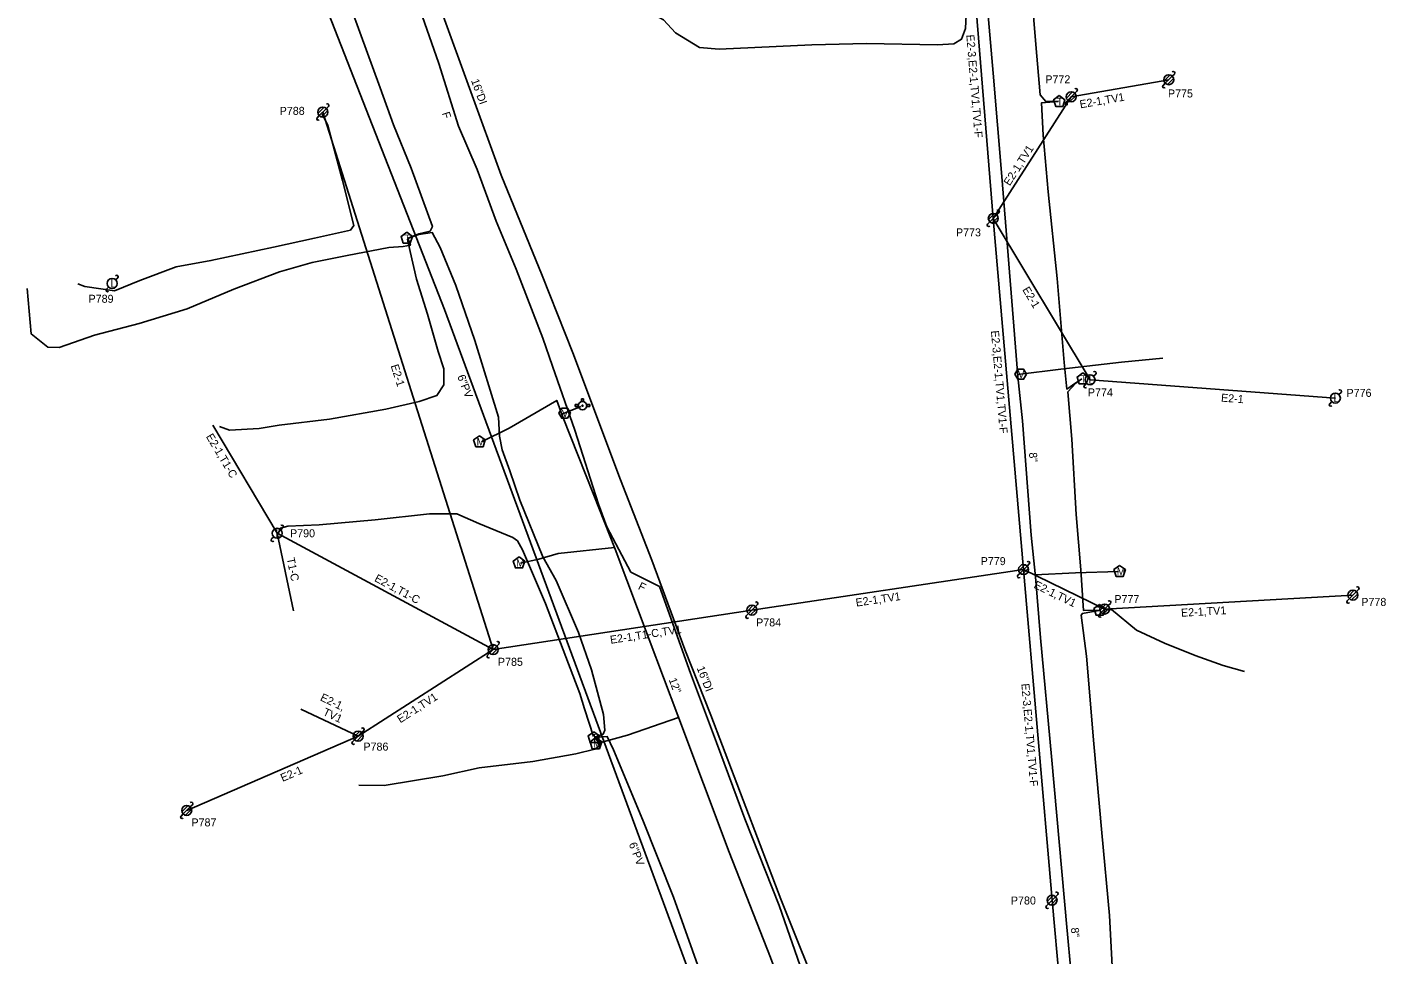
# Model space of a CAD drawing. Extents: x 1741604 to 1825760, y 1164229 to 1194908.
# Drawn here: x 1755844 to 1756523, y 1167516 to 1167980 of the extents above; entities that cross this region are included whole.
import ezdxf

# ---------------------------------------------------------------- set-up
doc = ezdxf.new("R2010")
doc.units = 0
for name, color, linetype in [('RD_EX_SU_Elec', 7, 'Continuous'), ('RD_EX_SU_H2O', 7, 'Continuous'), ('RD_EX_SU_Ovhd', 7, 'Continuous'), ('RD_EX_SU_Pole', 7, 'Continuous'), ('RD_EX_SU_Sewer', 7, 'Continuous'), ('RD_EX_SU_Telecom', 7, 'Continuous'), ('RD_EX_SU_TX_H2O', 7, 'Continuous'), ('RD_EX_SU_TX_Pole', 7, 'Continuous'), ('RD_EX_SU_TX_Sewer', 7, 'Continuous'), ('RD_EX_SU_TX_Telecom', 7, 'Continuous')]:
    doc.layers.add(name, color=color, linetype=linetype)

# ---------------------------------------------------------------- blocks, each defined once
blk = doc.blocks.new('SUE_TPP')
at = {"layer": 'RD_EX_SU_Telecom'}
blk.add_lwpolyline([(0, 3), (-2.85, 0.93), (-1.76, -2.43), (1.76, -2.43), (2.85, 0.93)], close=True, dxfattribs=at)
blk.add_text('T', height=3.75, dxfattribs=at).set_placement((-1.25, -1.88))
blk = doc.blocks.new('SUE_WV')
at = {"layer": 'RD_EX_SU_H2O'}
blk.add_lwpolyline([(2.89, 0), (1.44, 2.5), (-1.44, 2.5), (-2.89, 0), (-1.44, -2.5), (1.44, -2.5)], close=True, dxfattribs=at)
blk.add_text('V', height=3.75, dxfattribs=at).set_placement((-1.43, -1.88))
blk = doc.blocks.new('SUE_WM')
at = {"layer": 'RD_EX_SU_H2O'}
blk.add_lwpolyline([(0, 3.05), (-2.9, 0.94), (-1.79, -2.47), (1.79, -2.47), (2.9, 0.94)], close=True, dxfattribs=at)
blk.add_text('M', height=3.75, dxfattribs=at).set_placement((-1.43, -1.88))
blk = doc.blocks.new('SUE_PP')
at = {"layer": 'RD_EX_SU_Pole'}
for p, q in [((-2.41, -0.65), (0.65, 2.41)), ((-1.77, -1.77), (1.77, 1.77)), ((-0.65, -2.41), (2.41, 0.65)), ((1.77, 1.77), (2.83, 2.83)), ((-2.83, -2.83), (-1.77, -1.77))]:
    blk.add_line(p, q, dxfattribs=at)
blk.add_circle((0, 0), 2.5, dxfattribs=at)
for centre, start, end in [((2.3, 3.36), 315, 135), ((-2.3, -3.36), 135, 315)]:
    blk.add_arc(centre, 0.75, start, end, dxfattribs=at)
blk = doc.blocks.new('SUE_WFH')
at = {"layer": 'RD_EX_SU_H2O'}
for p, q in [((-2.01, 0.6), (-3.65, 0.6)), ((-3.65, 0.6), (-3.65, -0.45)), ((-0.48, 3.38), (-0.48, 2.04)), ((0.57, 3.38), (-0.48, 3.38)), ((0.57, 2.02), (0.57, 3.38)), ((3.7, 0.6), (2.01, 0.6)), ((3.7, -0.45), (3.7, 0.6)), ((-3.65, -0.45), (-2.05, -0.45)), ((2.05, -0.45), (3.7, -0.45))]:
    blk.add_line(p, q, dxfattribs=at)
for radius in [2.1, 0.263]:
    blk.add_circle((0, 0), radius, dxfattribs=at)
for start, end in [(163.3387, 192.31502), (74.24552, 103.21276), (347.68498, 16.6613)]:
    blk.add_arc((0, 0), 2.1, start, end, dxfattribs=at)

msp = doc.modelspace()

# ---------------------------------------------------------------- linework, layer by layer
at = {"layer": 'RD_EX_SU_Elec'}
msp.add_lwpolyline([(1755869.57, 1167851.16), (1755873.19, 1167849.88), (1755887.92, 1167847.77), (1755900.58, 1167852.96), (1755918.67, 1167859.68), (1755936.12, 1167862.87), (1755967.46, 1167869.61), (1755987.87, 1167873.98), (1756005.8, 1167878.1), (1756007.57, 1167880.39), (1756001.85, 1167902.91), (1755994.55, 1167930.43), (1755991.77, 1167936.28)], dxfattribs=at)
at = {"layer": 'RD_EX_SU_H2O'}
msp.add_line((1756111.54, 1167786.08), (1756120.89, 1167789.84), dxfattribs=at)
for points in [[(1756317.85, 1168067.08), (1756319.54, 1168050.19), (1756320.11, 1168042.67), (1756320.97, 1168030.07), (1756323.39, 1167998.84), (1756327.05, 1167956.56), (1756331.25, 1167904.83), (1756337.4, 1167830.13), (1756339.37, 1167804.89), (1756341.64, 1167782.73), (1756346.05, 1167725.54), (1756348.16, 1167704.76), (1756350.69, 1167674.25), (1756356.07, 1167614.92), (1756363.99, 1167527.76)], [(1756050.84, 1167988.86), (1756081.08, 1167905.61), (1756101.58, 1167855.44), (1756116.98, 1167816.66), (1756140.78, 1167753.22), (1756156.44, 1167713.09), (1756172.97, 1167668.41), (1756185.91, 1167635.6), (1756220.9, 1167543.58), (1756264.25, 1167435.38), (1756279.82, 1167397.12), (1756291.55, 1167363.49), (1756304.82, 1167319.34), (1756315.11, 1167296.28), (1756338.43, 1167239.43), (1756353.36, 1167188.5), (1756363.56, 1167189.08), (1756377.88, 1167188.77), (1756395.74, 1167189.62), (1756414.79, 1167190.46), (1756429.52, 1167190.99), (1756434.13, 1167122.57), (1756440.84, 1167042.69)], [(1756339.29, 1167805.94), (1756360.77, 1167808.6), (1756391.2, 1167811.99), (1756411.72, 1167814.03)], [(1756071.31, 1167772.16), (1756085.11, 1167779.07), (1756108.91, 1167792.94), (1756111.78, 1167785), (1756127.48, 1167745.51), (1756138.1, 1167718.5), (1756155.05, 1167673.34), (1756169.44, 1167635.39), (1756195.1, 1167567.1), (1756215.65, 1167514.35), (1756247.83, 1167428.43), (1756274.14, 1167357.35), (1756290.72, 1167313.58), (1756321.91, 1167230.75), (1756342.14, 1167174.56), (1756357.52, 1167133.56), (1756360.24, 1167126.4), (1756375.13, 1167136.28), (1756391.03, 1167147.63), (1756398.81, 1167147.78)], [(1756090.76, 1167711.58), (1756099.91, 1167713.6), (1756109.61, 1167716.33), (1756137.76, 1167719.35)], [(1756348.06, 1167705.73), (1756368.09, 1167706.65), (1756389.58, 1167707.36)], [(1756129.1, 1167621.41), (1756144.22, 1167625.61), (1756169.8, 1167634.44)], [(1756363.91, 1167527.82), (1756365.79, 1167507.89), (1756368.78, 1167467.42), (1756370.98, 1167441.15), (1756376.52, 1167385.51), (1756383.76, 1167307.51), (1756390.19, 1167237.32), (1756392.83, 1167205.42), (1756394.81, 1167177.82), (1756398.97, 1167146.58), (1756403.93, 1167098.11), (1756407.85, 1167047.93), (1756412.78, 1166988.79), (1756417.67, 1166944.94), (1756423.69, 1166896.82), (1756432.52, 1166846.14), (1756436.46, 1166827.08), (1756441.46, 1166798.75), (1756455, 1166743.89), (1756461.58, 1166718.69), (1756465.96, 1166702.52), (1756470.95, 1166683.5), (1756477.35, 1166658.41), (1756487.5, 1166618.6)]]:
    msp.add_lwpolyline(points, dxfattribs=at)
at = {"layer": 'RD_EX_SU_Ovhd'}
for p, q in [((1756317.86, 1167996.94), (1756327.05, 1167883.97)), ((1756366, 1167944.76), (1756414.72, 1167953.29)), ((1756327.05, 1167883.97), (1756366, 1167944.76)), ((1755992.03, 1167937.09), (1756077.13, 1167668.31)), ((1756327.05, 1167883.97), (1756342.18, 1167708.36)), ((1756327.05, 1167883.97), (1756375.39, 1167803.26)), ((1756375.39, 1167803.26), (1756497.97, 1167794.1)), ((1755937.06, 1167780.6), (1755969.27, 1167726.49)), ((1755969.27, 1167726.49), (1756077.13, 1167668.31)), ((1755969.27, 1167726.49), (1755977.32, 1167687.7)), ((1756206.43, 1167688.08), (1756342.18, 1167708.36)), ((1756342.18, 1167708.36), (1756356.4, 1167543.03)), ((1756342.18, 1167708.36), (1756382.71, 1167688.62)), ((1756382.71, 1167688.62), (1756506.75, 1167695.61)), ((1756077.13, 1167668.31), (1756206.43, 1167688.08)), ((1756009.64, 1167625.05), (1756077.13, 1167668.31)), ((1755981.08, 1167638.61), (1756009.64, 1167625.05)), ((1755924.02, 1167587.93), (1756009.64, 1167625.05)), ((1756356.4, 1167543.03), (1756373.78, 1167356.82))]:
    msp.add_line(p, q, dxfattribs=at)
at = {"layer": 'RD_EX_SU_Pole'}
for p, q in [((1756416.48, 1167955.06), (1756417.54, 1167956.12)), ((1756411.89, 1167950.46), (1756412.95, 1167951.52)), ((1756412.3, 1167952.64), (1756415.36, 1167955.71)), ((1756412.95, 1167951.52), (1756416.48, 1167955.06)), ((1756414.07, 1167950.88), (1756417.13, 1167953.94)), ((1756363.17, 1167941.93), (1756364.24, 1167942.99)), ((1756363.59, 1167944.11), (1756366.65, 1167947.17)), ((1756364.24, 1167942.99), (1756367.77, 1167946.52)), ((1756365.36, 1167942.34), (1756368.42, 1167945.4)), ((1756367.77, 1167946.52), (1756368.83, 1167947.59)), ((1755989.61, 1167936.44), (1755992.67, 1167939.51)), ((1755990.26, 1167935.32), (1755993.8, 1167938.86)), ((1755991.38, 1167934.68), (1755994.44, 1167937.74)), ((1755993.8, 1167938.86), (1755994.86, 1167939.92)), ((1755989.2, 1167934.26), (1755990.26, 1167935.32)), ((1756324.22, 1167881.14), (1756325.28, 1167882.2)), ((1756324.63, 1167883.32), (1756327.69, 1167886.38)), ((1756325.28, 1167882.2), (1756328.81, 1167885.74)), ((1756326.4, 1167881.56), (1756329.46, 1167884.62)), ((1756328.81, 1167885.74), (1756329.87, 1167886.8)), ((1755888.51, 1167853.18), (1755889.57, 1167854.24)), ((1755883.92, 1167848.58), (1755884.98, 1167849.64)), ((1756372.56, 1167800.43), (1756373.62, 1167801.5)), ((1756377.16, 1167805.03), (1756378.22, 1167806.09)), ((1756499.74, 1167795.87), (1756500.8, 1167796.93)), ((1756495.14, 1167791.27), (1756496.21, 1167792.33)), ((1755971.04, 1167728.26), (1755972.1, 1167729.32)), ((1755966.44, 1167723.67), (1755967.5, 1167724.73))]:
    msp.add_line(p, q, dxfattribs=at)
for centre in [(1756414.72, 1167953.29), (1756366, 1167944.76), (1755992.03, 1167937.09), (1756327.05, 1167883.97), (1755886.75, 1167851.41), (1756375.39, 1167803.26), (1756497.97, 1167794.1), (1755969.27, 1167726.49)]:
    msp.add_circle(centre, 2.5, dxfattribs=at)
for centre, start, end in [((1756417.01, 1167956.65), 315, 135), ((1756412.42, 1167949.93), 135, 315), ((1756368.3, 1167948.12), 315, 135), ((1755994.33, 1167940.45), 315, 135), ((1756363.71, 1167941.4), 135, 315), ((1755989.73, 1167933.73), 135, 315), ((1756329.34, 1167887.33), 315, 135), ((1756324.75, 1167880.61), 135, 315), ((1755889.04, 1167854.77), 315, 135), ((1755884.45, 1167848.05), 135, 315), ((1756377.69, 1167806.62), 315, 135), ((1756373.09, 1167799.9), 135, 315), ((1756500.27, 1167797.46), 315, 135), ((1756495.67, 1167790.74), 135, 315), ((1755971.57, 1167729.85), 315, 135), ((1755966.97, 1167723.14), 135, 315)]:
    msp.add_arc(centre, 0.75, start, end, dxfattribs=at)
at = {"layer": 'RD_EX_SU_Sewer'}
for points in [[(1755918.27, 1168182.4), (1756052.9, 1167838.38)], [(1756052.9, 1167838.38), (1756224.72, 1167372.47), (1756323.52, 1167096.55), (1756376.52, 1166947.01), (1756475.17, 1166587.83)]]:
    msp.add_lwpolyline(points, dxfattribs=at)
at = {"layer": 'RD_EX_SU_Telecom'}
for points in [[(1756338.16, 1168189.78), (1756333.21, 1168189.81), (1756330.86, 1168187.79), (1756330.68, 1168184.52), (1756333.54, 1168148.9), (1756336.25, 1168107.92), (1756338.14, 1168089.1), (1756341.61, 1168045.19), (1756342.02, 1168029.89), (1756344.16, 1168021.72), (1756348.34, 1167970.86), (1756350.41, 1167945.66), (1756353.23, 1167942.43), (1756359.64, 1167942.51)], [(1756034.61, 1167874.06), (1756040.08, 1167876.29), (1756045.63, 1167877.54), (1756046.82, 1167879.95), (1756036.25, 1167909.07), (1756027.29, 1167930.71), (1756020.62, 1167949.2), (1756010.49, 1167977), (1756001.55, 1168001.89), (1755990.3, 1168030.08), (1755982.09, 1168049.19), (1755980.19, 1168050.16), (1755973.48, 1168046.32)], [(1756158.59, 1167985.22), (1756162.2, 1167983.17), (1756168.33, 1167976.76), (1756180.21, 1167969.34), (1756190.12, 1167968.53), (1756236.31, 1167970.8), (1756263.75, 1167971.46), (1756299.2, 1167970.68), (1756307.27, 1167971.19), (1756311.09, 1167973.51), (1756313.18, 1167978.88), (1756313.61, 1167989.06), (1756314.16, 1167997.74), (1756316.41, 1167997.29)], [(1756039.32, 1167991.87), (1756050.05, 1167961.32), (1756059.83, 1167929.98), (1756069.2, 1167908.38), (1756078.7, 1167882.57), (1756088.71, 1167858.62), (1756102.02, 1167823.98), (1756106.74, 1167810.01), (1756117.97, 1167778.02), (1756129.82, 1167741.09), (1756134.01, 1167729.65), (1756145.95, 1167707.06), (1756160.25, 1167699.88), (1756175.68, 1167656.58), (1756188.68, 1167621.82), (1756202.92, 1167583.73), (1756219.98, 1167540.39), (1756233.26, 1167502.58)], [(1756359.48, 1167942.44), (1756351.11, 1167941.7), (1756351.95, 1167925.63), (1756354.4, 1167897.16), (1756358.92, 1167853.95), (1756362.5, 1167811.93), (1756363.77, 1167798.56), (1756368.25, 1167801.76), (1756371.25, 1167803.66)], [(1756034.53, 1167873.86), (1756040.08, 1167875.94), (1756046.7, 1167876.83), (1756050.72, 1167869.39), (1756058.52, 1167850.38), (1756068.07, 1167822.86), (1756079.87, 1167784.61), (1756080.23, 1167775.03), (1756081.57, 1167768.15), (1756085.55, 1167757.65), (1756090.48, 1167743.05), (1756101.96, 1167714.71), (1756108.69, 1167702.97), (1756119.73, 1167676.96), (1756126.29, 1167658.16), (1756132.36, 1167635.96), (1756132.95, 1167628.04), (1756132.08, 1167626), (1756127.76, 1167624.57)], [(1755844.3, 1167848.97), (1755846.32, 1167826.16), (1755854.61, 1167819.58), (1755860.32, 1167819.34), (1755877.92, 1167825.49), (1755900.21, 1167831.38), (1755924.21, 1167838.68), (1755947.5, 1167848.57), (1755970.39, 1167857.17), (1755986.75, 1167861.86), (1756004.23, 1167865.47), (1756024.94, 1167869.39), (1756032.13, 1167869.89), (1756035.8, 1167870.54), (1756034.7, 1167873.57)], [(1756034.35, 1167873.52), (1756035.66, 1167867.47), (1756038.81, 1167853.61), (1756044.27, 1167836.05), (1756049.68, 1167817.45), (1756052.45, 1167808.8), (1756052.53, 1167800.7), (1756049, 1167795.32), (1756040.22, 1167792.38), (1756023.57, 1167788.59), (1755995.41, 1167783.6), (1755970.21, 1167780.51), (1755960.21, 1167778.83), (1755945.42, 1167778.1), (1755940.33, 1167779.88)], [(1756371.22, 1167803.69), (1756368.25, 1167801.64), (1756364.32, 1167797.23), (1756366.22, 1167773.48), (1756368.54, 1167735.91), (1756370.77, 1167708.23), (1756372.16, 1167687.85), (1756379.89, 1167688.13)], [(1755969.89, 1167726.65), (1755970.91, 1167729.13), (1755974.51, 1167729.99), (1755990.23, 1167730.65), (1756018.14, 1167733.24), (1756045.36, 1167736.26), (1756058.92, 1167736.26), (1756070, 1167731.46), (1756087.05, 1167724.47), (1756089.36, 1167722.65), (1756091.74, 1167718.3), (1756103.28, 1167691.37), (1756113.45, 1167664.75), (1756120.39, 1167646.36), (1756122.75, 1167638.68), (1756127.3, 1167624.92)], [(1756379.84, 1167687.97), (1756371.61, 1167686.43), (1756371.04, 1167685.63), (1756373.7, 1167665.14), (1756377.25, 1167621.18), (1756381.27, 1167576.66), (1756385.09, 1167535.47), (1756386.8, 1167503.76), (1756389.57, 1167497.42), (1756391.33, 1167485.77), (1756391.87, 1167476.99), (1756394.9, 1167432.18), (1756398.78, 1167388.08), (1756403.08, 1167343.13), (1756406.4, 1167302.54), (1756409.67, 1167260.19), (1756412.65, 1167233.18), (1756415.46, 1167205.3), (1756418.94, 1167164.23), (1756422.06, 1167133.72), (1756424.59, 1167105.7), (1756427.38, 1167076.61), (1756430.2, 1167046.88)], [(1756383.1, 1167688.32), (1756386.12, 1167688.46), (1756398.58, 1167678.13), (1756412.62, 1167671.56), (1756428, 1167665.46), (1756441.94, 1167660.34), (1756452.56, 1167657.36)], [(1756010.05, 1167600.63), (1756022.7, 1167600.39), (1756052.08, 1167605.26), (1756070.07, 1167609.2), (1756096.95, 1167612.44), (1756118.49, 1167616.28), (1756127.92, 1167618.51), (1756130.07, 1167620.07), (1756130.01, 1167622.26), (1756127.75, 1167624.11)], [(1756127.86, 1167624.47), (1756134.12, 1167624.83), (1756137.29, 1167618.27), (1756151.91, 1167583.07), (1756167.31, 1167544.54), (1756181.93, 1167503.45), (1756190.52, 1167477.21), (1756195.07, 1167463.69), (1756198.66, 1167456.38), (1756204.33, 1167443.81), (1756202.19, 1167439.67), (1756198.01, 1167436.74)]]:
    msp.add_lwpolyline(points, dxfattribs=at)

# ---------------------------------------------------------------- block references
at = {"layer": 'RD_EX_SU_H2O'}
for name, p in [('SUE_WV', (1756340.74, 1167806.05)), ('SUE_WFH', (1756121.78, 1167790.32)), ('SUE_WV', (1756112.82, 1167786.49)), ('SUE_WM', (1756070.3, 1167772.21)), ('SUE_WM', (1756090.06, 1167711.63)), ('SUE_WM', (1756390.2, 1167707.41)), ('SUE_WM', (1756128.47, 1167621.27))]:
    msp.add_blockref(name, p, dxfattribs=at)
at = {"layer": 'RD_EX_SU_Pole'}
for p in [(1756342.18, 1167708.36), (1756506.75, 1167695.61), (1756206.43, 1167688.08), (1756382.71, 1167688.62), (1756077.13, 1167668.31), (1756009.64, 1167625.05), (1755924.02, 1167587.93), (1756356.4, 1167543.03)]:
    msp.add_blockref('SUE_PP', p, dxfattribs=at)
at = {"layer": 'RD_EX_SU_Telecom'}
for p in [(1756360.03, 1167942.36), (1756033.97, 1167874.01), (1756371.77, 1167803.65), (1756380.17, 1167687.93), (1756127.44, 1167624.3)]:
    msp.add_blockref('SUE_TPP', p, dxfattribs=at)

# ---------------------------------------------------------------- texts
at = {"layer": 'RD_EX_SU_Ovhd'}
for s, rotation, p in [('E2-3,E2-1,TV1,TV1-F', 274.64996, (1756313.57, 1167975.68)), ('E2-1,TV1', 9.9369, (1756370.58, 1167938.96)), ('E2-1,TV1', 57.34496, (1756335.26, 1167899.93)), ('E2-1', 300.92124, (1756341.41, 1167848.31)), ('E2-3,E2-1,TV1,TV1-F', 274.92539, (1756325.87, 1167827.73)), ('E2-1', 287.56914, (1756025.89, 1167810.27)), ('E2-1', 355.72628, (1756440.74, 1167792.36)), ('E2-1,T1-C', 300.76396, (1755933.49, 1167774.88)), ('T1-C', 281.71511, (1755973.92, 1167713.91)), ('E2-1,T1-C', 331.65738, (1756017.47, 1167702.77)), ('E2-1,TV1', 334.02741, (1756346.93, 1167699.37)), ('E2-1,TV1', 8.49892, (1756258.61, 1167689.81)), ('E2-1,TV1', 3.22525, (1756420.98, 1167684.76)), ('E2-1,T1-C,TV1', 8.68997, (1756135.88, 1167671.22)), ('E2-3,E2-1,TV1,TV1-F', 274.91654, (1756341.07, 1167651.24)), ('E2-1,', 334.60195, (1755990.37, 1167643.05)), ('E2-1,TV1', 32.66151, (1756030.74, 1167631.45)), ('TV1', 334.60195, (1755991.71, 1167635.78)), ('E2-1', 23.4387, (1755971.93, 1167602.16))]:
    msp.add_text(s, height=4, rotation=rotation, dxfattribs=at).set_placement(p)
at = {"layer": 'RD_EX_SU_Pole'}
for p in [(1755885.88, 1167849.41), (1756374.53, 1167801.26), (1756497.11, 1167792.1), (1755968.41, 1167724.49)]:
    msp.add_text('L', height=4, dxfattribs=at).set_placement(p)
at = {"layer": 'RD_EX_SU_TX_H2O'}
for s, rotation, p in [('16"DI', 289.9624, (1756066.03, 1167952.9)), ('8"', 274.41179, (1756344.87, 1167766.81)), ('16"DI', 291.54117, (1756178.76, 1167659.18)), ('12"', 290.77175, (1756164.77, 1167653.35)), ('8"', 275.38113, (1756365.79, 1167529.19))]:
    msp.add_text(s, height=4, rotation=rotation, dxfattribs=at).set_placement(p)
at = {"layer": 'RD_EX_SU_TX_Pole'}
for s, p in [('P772', (1756353.04, 1167951.48)), ('P775', (1756414.33, 1167944.42)), ('P788', (1755970.47, 1167935.72)), ('P773', (1756308.4, 1167874.96)), ('P789', (1755874.97, 1167841.76)), ('P774', (1756374.31, 1167794.95)), ('P776', (1756503.56, 1167794.7)), ('P790', (1755975.64, 1167724.51)), ('P779', (1756320.76, 1167710.59)), ('P777', (1756387.55, 1167691.6)), ('P778', (1756510.94, 1167690.19)), ('P784', (1756208.54, 1167679.93)), ('P785', (1756079.53, 1167660.23)), ('P786', (1756012.31, 1167617.83)), ('P787', (1755926.38, 1167579.94)), ('P780', (1756335.85, 1167540.89))]:
    msp.add_text(s, height=4, dxfattribs=at).set_placement(p)
at = {"layer": 'RD_EX_SU_TX_Sewer'}
for p in [(1756059.15, 1167804.94), (1756144.86, 1167571.14)]:
    msp.add_text('6"PV', height=4, rotation=290.73948, dxfattribs=at).set_placement(p)
at = {"layer": 'RD_EX_SU_TX_Telecom'}
for rotation, p in [(287.32422, (1756051.5, 1167936.53)), (333.33694, (1756149.25, 1167698.69))]:
    msp.add_text('F', height=4, rotation=rotation, dxfattribs=at).set_placement(p)

doc.saveas('drawing.dxf')
